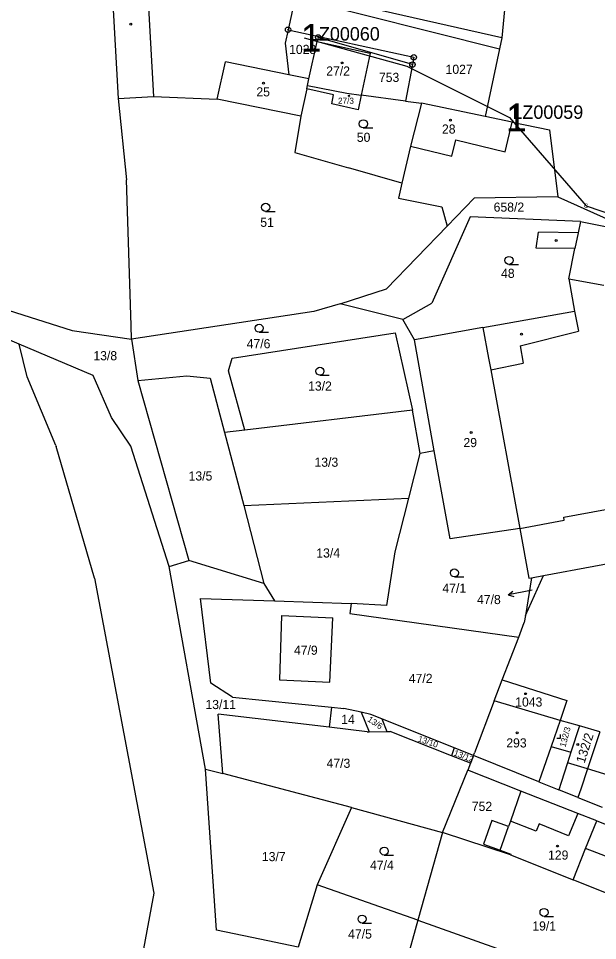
# Model space of a CAD drawing. Extents: x -738131 to -734179, y -1033447 to -1030078.
# Drawn here: x -736374.8 to -736266.9, y -1032166.9 to -1031995.2 of the extents above; entities that cross this region are included whole.
import ezdxf

# ---------------------------------------------------------------- set-up
doc = ezdxf.new("R2010")
doc.units = 0
for name, color, linetype in [('ftf_2010', 7, 'Continuous'), ('ftf_2050', 7, 'Continuous'), ('ftf_3010', 7, 'Continuous'), ('ftf_3010_ftf_3010_gtda_3015_gtda_3015_1', 7, 'Continuous'), ('ftf_3240', 7, 'Continuous'), ('Vrstva 1', 7, 'Continuous'), ('Vrstva 2', 7, 'Continuous'), ('Vrstva 3', 7, 'Continuous'), ('Vrstva 4', 7, 'Continuous'), ('Vrstva 5', 7, 'Continuous'), ('Vrstva 7', 7, 'Continuous'), ('Vrstva 8', 7, 'Continuous')]:
    doc.layers.add(name, color=color, linetype=linetype)

msp = doc.modelspace()

# ---------------------------------------------------------------- linework, layer by layer
at = {"layer": 'ftf_2010'}
msp.add_lwpolyline([(-736321.57, -1031998.83), (-736302.42, -1032004.14), (-736283.32, -1032013.66)], dxfattribs=at)
at = {"layer": 'ftf_2050'}
msp.add_lwpolyline([(-736283.32, -1032013.66), (-736269.03, -1032030.1), (-736251.9, -1032035.95), (-736234.64, -1032039.77)], dxfattribs=at)
at = {"layer": 'Vrstva 1'}
for points in [[(-736357.65, -1031984.69), (-736356.24, -1032010.13)], [(-736323.24, -1031991.27), (-736324.58, -1031997.32)], [(-736323.24, -1031991.27), (-736285.15, -1032000.89)], [(-736284.71, -1031998.81), (-736311.45, -1031992.83)], [(-736284.09, -1031992.29), (-736284.71, -1031998.81)], [(-736324.58, -1031997.32), (-736325.13, -1031999.84)], [(-736324.58, -1031997.32), (-736301.14, -1032002.45)], [(-736325.13, -1031999.84), (-736324.41, -1032005.73)], [(-736320.68, -1032006.49), (-736319.14, -1031999.54)], [(-736318.96, -1031998.76), (-736319.14, -1031999.54)], [(-736319.14, -1031999.54), (-736309.26, -1032001.7)], [(-736301.39, -1032003.81), (-736318.96, -1031998.76)], [(-736284.71, -1031998.81), (-736285.15, -1032000.89)], [(-736309.26, -1032001.7), (-736310.95, -1032009.49)], [(-736285.15, -1032000.89), (-736287.83, -1032013.47)], [(-736301.14, -1032002.45), (-736301.39, -1032003.81)], [(-736301.39, -1032003.81), (-736302.66, -1032010.6)], [(-736320.68, -1032006.49), (-736324.41, -1032005.73)], [(-736320.95, -1032007.71), (-736320.68, -1032006.49)], [(-736321.09, -1032008.35), (-736322.22, -1032013.44)], [(-736321.09, -1032008.35), (-736320.95, -1032007.71)], [(-736316.09, -1032009.46), (-736321.09, -1032008.35)], [(-736320.95, -1032007.71), (-736313.62, -1032009.13)], [(-736356.24, -1032010.13), (-736349.64, -1032009.76)], [(-736356.24, -1032010.13), (-736354.69, -1032025.26)], [(-736349.64, -1032009.76), (-736337.8, -1032010.25)], [(-736322.22, -1032013.44), (-736337.8, -1032010.25)], [(-736316.44, -1032011.15), (-736316.09, -1032009.46)], [(-736313.62, -1032009.13), (-736310.95, -1032009.49)], [(-736310.95, -1032009.49), (-736311.54, -1032012.22)], [(-736302.66, -1032010.6), (-736310.95, -1032009.49)], [(-736311.54, -1032012.22), (-736316.44, -1032011.15)], [(-736302.66, -1032010.6), (-736299.69, -1032010.99)], [(-736299.69, -1032010.99), (-736301.74, -1032018.99)], [(-736287.83, -1032013.47), (-736299.69, -1032010.99)], [(-736322.22, -1032013.44), (-736323.31, -1032020.18)], [(-736282.79, -1032014.52), (-736287.83, -1032013.47)], [(-736282.79, -1032014.52), (-736275.85, -1032015.97)], [(-736275.85, -1032015.97), (-736274.28, -1032028.47)], [(-736323.31, -1032020.18), (-736313.32, -1032023.06)], [(-736301.74, -1032018.99), (-736303.36, -1032025.92)], [(-736303.36, -1032025.92), (-736313.32, -1032023.06)], [(-736353.81, -1032052.38), (-736354.69, -1032025.26)], [(-736303.36, -1032025.92), (-736304.02, -1032028.72)], [(-736304.02, -1032028.72), (-736295.89, -1032030.28)], [(-736289.89, -1032028.72), (-736294.94, -1032033.92)], [(-736274.28, -1032028.47), (-736289.89, -1032028.72)], [(-736274.28, -1032028.47), (-736259.19, -1032035.19)], [(-736295.89, -1032030.28), (-736294.94, -1032033.92)], [(-736290.66, -1032032.19), (-736297.75, -1032048.25)], [(-736270.09, -1032033.01), (-736290.66, -1032032.19)], [(-736294.94, -1032033.92), (-736306.24, -1032045.57)], [(-736270.09, -1032033.01), (-736270.52, -1032035.12)], [(-736270.09, -1032033.01), (-736259.19, -1032035.19)], [(-736278.36, -1032038), (-736277.91, -1032035)], [(-736270.52, -1032035.12), (-736277.91, -1032035)], [(-736271.11, -1032038.07), (-736278.36, -1032038)], [(-736272.24, -1032043.71), (-736271.11, -1032038.07)], [(-736272.24, -1032043.71), (-736271.17, -1032049.76)], [(-736374.67, -1032055.87), (-736398.21, -1032045.87)], [(-736314.89, -1032048.34), (-736306.24, -1032045.57)], [(-736383.28, -1032047.51), (-736364.84, -1032053.35)], [(-736319.79, -1032049.77), (-736353.73, -1032054.93)], [(-736314.89, -1032048.34), (-736319.79, -1032049.77)], [(-736303.21, -1032051.27), (-736314.89, -1032048.34)], [(-736303.21, -1032051.27), (-736297.75, -1032048.25)], [(-736288.25, -1032052.79), (-736271.17, -1032049.76)], [(-736301.04, -1032055.06), (-736303.21, -1032051.27)], [(-736353.73, -1032054.93), (-736353.81, -1032052.38)], [(-736288.25, -1032052.79), (-736301.04, -1032055.06)], [(-736364.84, -1032053.35), (-736353.73, -1032054.93)], [(-736353.73, -1032054.93), (-736352.57, -1032062.65)], [(-736334.98, -1032058.48), (-736304.59, -1032053.78)], [(-736304.59, -1032053.78), (-736301.36, -1032068.16)], [(-736373.2, -1032061.95), (-736374.67, -1032055.87)], [(-736360.88, -1032061.73), (-736374.67, -1032055.87)], [(-736297.33, -1032075.77), (-736301.04, -1032055.06)], [(-736335.66, -1032060.83), (-736334.98, -1032058.48)], [(-736357.46, -1032069.53), (-736360.88, -1032061.73)], [(-736352.57, -1032062.65), (-736343.45, -1032061.78)], [(-736343.45, -1032061.78), (-736339.08, -1032062.24)], [(-736332.63, -1032071.9), (-736335.66, -1032060.83)], [(-736367.85, -1032074.72), (-736373.2, -1032061.95)], [(-736352.57, -1032062.65), (-736343.07, -1032096.14)], [(-736339.08, -1032062.24), (-736336.39, -1032072.35)], [(-736301.36, -1032068.16), (-736332.63, -1032071.9)], [(-736299.95, -1032076.23), (-736301.36, -1032068.16)], [(-736353.87, -1032074.87), (-736357.46, -1032069.53)], [(-736332.63, -1032071.9), (-736336.39, -1032072.35)], [(-736336.39, -1032072.35), (-736332.79, -1032085.91)], [(-736367.85, -1032074.72), (-736367.79, -1032074.92)], [(-736360.62, -1032099.46), (-736367.79, -1032074.92)], [(-736346.73, -1032097.26), (-736353.87, -1032074.87)], [(-736302.07, -1032084.56), (-736299.95, -1032076.23)], [(-736297.33, -1032075.77), (-736299.95, -1032076.23)], [(-736294.39, -1032092.15), (-736297.33, -1032075.77)], [(-736332.79, -1032085.91), (-736302.07, -1032084.56)], [(-736332.79, -1032085.91), (-736329.06, -1032100.43)], [(-736304.61, -1032094.54), (-736302.07, -1032084.56)], [(-736281.4, -1032090.23), (-736294.39, -1032092.15)], [(-736281.4, -1032090.23), (-736279.68, -1032099.47)], [(-736276.96, -1032098.96), (-736239.45, -1032092.03)], [(-736346.73, -1032097.26), (-736343.07, -1032096.14)], [(-736329.06, -1032100.43), (-736343.07, -1032096.14)], [(-736306.15, -1032104.53), (-736304.61, -1032094.54)], [(-736339.94, -1032135.02), (-736346.73, -1032097.26)], [(-736360.62, -1032099.46), (-736351.12, -1032149.84)], [(-736280.33, -1032106.39), (-736276.96, -1032098.96)], [(-736279.21, -1032099.38), (-736280.33, -1032106.39)], [(-736279.68, -1032099.47), (-736279.21, -1032099.38)], [(-736279.21, -1032099.38), (-736276.96, -1032098.96)], [(-736329.06, -1032100.43), (-736327.12, -1032103.7)], [(-736338.98, -1032119.02), (-736340.89, -1032103.24)], [(-736340.89, -1032103.24), (-736327.12, -1032103.7)], [(-736327.12, -1032103.7), (-736312.79, -1032104.16)], [(-736312.79, -1032104.16), (-736313.07, -1032106.06)], [(-736306.15, -1032104.53), (-736312.79, -1032104.16)], [(-736325.79, -1032106.38), (-736326.18, -1032118.41)], [(-736325.79, -1032106.38), (-736316.26, -1032106.81)], [(-736313.07, -1032106.06), (-736281.58, -1032110.42)], [(-736280.33, -1032106.39), (-736280.55, -1032107.74)], [(-736316.77, -1032118.81), (-736316.26, -1032106.81)], [(-736281.58, -1032110.42), (-736280.55, -1032107.74)], [(-736284.65, -1032118.38), (-736281.58, -1032110.42)], [(-736326.18, -1032118.41), (-736316.77, -1032118.81)], [(-736286.14, -1032122.3), (-736284.65, -1032118.38)], [(-736284.65, -1032118.38), (-736272.65, -1032122.22)], [(-736334.94, -1032121.6), (-736338.98, -1032119.02)], [(-736334.94, -1032121.6), (-736316.47, -1032123.48)], [(-736316.47, -1032123.48), (-736316.94, -1032127.22)], [(-736316.47, -1032123.48), (-736314.21, -1032123.71)], [(-736286.14, -1032122.3), (-736289.83, -1032132)], [(-736273.89, -1032125.98), (-736286.14, -1032122.3)], [(-736272.65, -1032122.22), (-736273.89, -1032125.98)], [(-736316.94, -1032127.22), (-736337.57, -1032124.78)], [(-736336.75, -1032135.82), (-736337.57, -1032124.78)], [(-736310.93, -1032124.43), (-736314.21, -1032123.71)], [(-736310.93, -1032124.43), (-736309.43, -1032128.06)], [(-736309.13, -1032124.82), (-736310.93, -1032124.43)], [(-736307.11, -1032125.63), (-736309.13, -1032124.82)], [(-736293.61, -1032131.06), (-736307.11, -1032125.63)], [(-736307.11, -1032125.63), (-736306.14, -1032128.03)], [(-736273.89, -1032125.98), (-736275.55, -1032130.78)], [(-736270.28, -1032126.95), (-736273.89, -1032125.98)], [(-736270.28, -1032126.95), (-736271.86, -1032131.86)], [(-736266.49, -1032128.05), (-736270.28, -1032126.95)], [(-736309.81, -1032128.06), (-736316.94, -1032127.22)], [(-736309.81, -1032128.06), (-736309.43, -1032128.06)], [(-736309.43, -1032128.06), (-736306.14, -1032128.03)], [(-736306.14, -1032128.03), (-736305.57, -1032128.03)], [(-736294.1, -1032132.52), (-736305.57, -1032128.03)], [(-736266.49, -1032128.05), (-736268.77, -1032134.98)], [(-736293.61, -1032131.06), (-736294.1, -1032132.52)], [(-736290.32, -1032132.38), (-736293.61, -1032131.06)], [(-736290.02, -1032132.5), (-736289.83, -1032132)], [(-736275.55, -1032130.78), (-736277.39, -1032136.12)], [(-736271.86, -1032131.86), (-736272.5, -1032133.84)], [(-736290.55, -1032133.91), (-736294.1, -1032132.52)], [(-736290.55, -1032133.91), (-736291.05, -1032135.21)], [(-736290.02, -1032132.5), (-736290.55, -1032133.91)], [(-736290.02, -1032132.5), (-736290.32, -1032132.38)], [(-736277.83, -1032137.39), (-736290.02, -1032132.5)], [(-736272.5, -1032133.84), (-736273.68, -1032137.51)], [(-736339.94, -1032135.02), (-736336.75, -1032135.82)], [(-736337.93, -1032165.02), (-736339.94, -1032135.02)], [(-736295.8, -1032146.81), (-736291.05, -1032135.21)], [(-736281.21, -1032139.1), (-736291.05, -1032135.21)], [(-736268.77, -1032134.98), (-736270.01, -1032138.74)], [(-736312.74, -1032142.19), (-736336.75, -1032135.82)], [(-736277.39, -1032136.12), (-736277.83, -1032137.39)], [(-736277.83, -1032137.39), (-736274.12, -1032138.88)], [(-736281.21, -1032139.1), (-736283.13, -1032144.72)], [(-736270.58, -1032143.29), (-736281.21, -1032139.1)], [(-736273.68, -1032137.51), (-736274.12, -1032138.88)], [(-736270.56, -1032140.31), (-736274.12, -1032138.88)], [(-736270.01, -1032138.74), (-736270.56, -1032140.31)], [(-736270.56, -1032140.31), (-736266.05, -1032142.12)], [(-736312.74, -1032142.19), (-736319.15, -1032156.54)], [(-736312.74, -1032142.19), (-736295.8, -1032146.81)], [(-736267.01, -1032144.65), (-736270.58, -1032143.29)], [(-736286.6, -1032144.61), (-736288.12, -1032148.99)], [(-736283.48, -1032145.72), (-736286.6, -1032144.61)], [(-736283.13, -1032144.72), (-736283.48, -1032145.72)], [(-736269.12, -1032149.8), (-736267.01, -1032144.65)], [(-736267.01, -1032144.65), (-736255.26, -1032149.31)], [(-736295.8, -1032146.81), (-736300.36, -1032163.17)], [(-736283.11, -1032150.98), (-736295.8, -1032146.81)], [(-736288.12, -1032148.99), (-736285.04, -1032150.08)], [(-736351.12, -1032149.84), (-736349.56, -1032158.09)], [(-736285.04, -1032150.08), (-736283.06, -1032150.84)], [(-736283.06, -1032150.84), (-736283.11, -1032150.98)], [(-736283.11, -1032150.98), (-736271.44, -1032155.66)], [(-736271.44, -1032155.66), (-736269.12, -1032149.8)], [(-736259.05, -1032160.59), (-736271.44, -1032155.66)], [(-736319.15, -1032156.54), (-736322.71, -1032168.15)], [(-736300.36, -1032163.17), (-736319.15, -1032156.54)], [(-736349.56, -1032158.09), (-736352.54, -1032173.8)], [(-736300.36, -1032163.17), (-736302.67, -1032171.47)], [(-736300.36, -1032163.17), (-736271.96, -1032173.23)], [(-736331.32, -1032166.39), (-736337.93, -1032165.02)], [(-736322.71, -1032168.15), (-736331.32, -1032166.39)]]:
    msp.add_lwpolyline(points, dxfattribs=at)
at = {"layer": 'Vrstva 3'}
for p, q in [((-736310.55, -1032015.6), (-736308.8, -1032015.6)), ((-736328.75, -1032031.15), (-736327, -1032031.15)), ((-736283.4, -1032041.03), (-736281.65, -1032041.03)), ((-736329.97, -1032053.66), (-736328.22, -1032053.66)), ((-736318.64, -1032061.66), (-736316.89, -1032061.66)), ((-736293.57, -1032099.22), (-736291.82, -1032099.22)), ((-736273.8, -1032129.24), (-736273.8, -1032128.57)), ((-736274.47, -1032129.24), (-736273.8, -1032129.24)), ((-736306.66, -1032151.03), (-736304.91, -1032151.03)), ((-736276.87, -1032162.45), (-736275.12, -1032162.45)), ((-736310.78, -1032163.69), (-736309.03, -1032163.69))]:
    msp.add_line(p, q, dxfattribs=at)
for centre in [(-736310.55, -1032014.85), (-736328.75, -1032030.4), (-736283.4, -1032040.28), (-736329.97, -1032052.91), (-736318.64, -1032060.91), (-736293.57, -1032098.47), (-736306.66, -1032150.28), (-736276.87, -1032161.7), (-736310.78, -1032162.94)]:
    msp.add_circle(centre, 0.75, dxfattribs=at)
at = {"layer": 'Vrstva 4'}
for points in [[(-736351.06, -1031984.32), (-736349.64, -1032009.76)], [(-736337.8, -1032010.25), (-736336.23, -1032003.31)], [(-736324.41, -1032005.73), (-736336.23, -1032003.31)], [(-736284.11, -1032020.04), (-736282.79, -1032014.52)], [(-736294.04, -1032020.84), (-736293.32, -1032017.83)], [(-736293.32, -1032017.83), (-736284.11, -1032020.04)], [(-736301.74, -1032018.99), (-736294.04, -1032020.84)], [(-736270.52, -1032035.12), (-736271.11, -1032038.07)], [(-736272.24, -1032043.71), (-736265.75, -1032044.88)], [(-736271.17, -1032049.76), (-736270.45, -1032053.47)], [(-736288.25, -1032052.79), (-736287.19, -1032058.5)], [(-736281.33, -1032056.18), (-736270.45, -1032053.47)], [(-736281.33, -1032056.18), (-736280.76, -1032059.4)], [(-736287.19, -1032058.5), (-736286.8, -1032060.63)], [(-736286.8, -1032060.63), (-736280.76, -1032059.4)], [(-736286.8, -1032060.63), (-736281.4, -1032090.23)], [(-736273.21, -1032088.09), (-736237.38, -1032081.5)], [(-736281.4, -1032090.23), (-736273.1, -1032088.68)], [(-736273.1, -1032088.68), (-736273.21, -1032088.09)], [(-736275.55, -1032130.78), (-736271.86, -1032131.86)], [(-736268.77, -1032134.98), (-736272.5, -1032133.84)], [(-736264.14, -1032136.41), (-736268.77, -1032134.98)], [(-736270.58, -1032143.29), (-736272.31, -1032147.46)], [(-736285.04, -1032150.08), (-736283.48, -1032145.72)], [(-736278.32, -1032146.59), (-736283.13, -1032144.72)], [(-736277.77, -1032145.21), (-736278.32, -1032146.59)], [(-736272.31, -1032147.46), (-736277.77, -1032145.21)], [(-736256.99, -1032154.45), (-736269.12, -1032149.8)]]:
    msp.add_lwpolyline(points, dxfattribs=at)
at = {"layer": 'Vrstva 5'}
for centre, radius in [((-736353.9, -1031996.27), 0.175), ((-736314.52, -1032003.52), 0.175), ((-736329.14, -1032007.27), 0.175), ((-736313.21, -1032009.64), 0.117), ((-736294.33, -1032014.18), 0.175), ((-736274.6, -1032036.57), 0.175), ((-736281.07, -1032054.01), 0.175), ((-736290.43, -1032072.31), 0.175), ((-736280.3, -1032120.97), 0.175), ((-736281.89, -1032128.25), 0.175), ((-736270.59, -1032130.41), 0.175), ((-736274.35, -1032149.34), 0.175)]:
    msp.add_circle(centre, radius, dxfattribs=at)
at = {"layer": 'Vrstva 7'}
for p, q in [((-736283.56, -1032102.58), (-736282.67, -1032101.89)), ((-736280.61, -1032102), (-736283.56, -1032102.58)), ((-736283.56, -1032102.58), (-736282.48, -1032102.88))]:
    msp.add_line(p, q, dxfattribs=at)
msp.add_lwpolyline([(-736279.05, -1032101.7), (-736280.61, -1032102)], dxfattribs=at)
at = {"layer": 'Vrstva 8'}
for centre, radius in [((-736324.58, -1031997.32), 0.5), ((-736324.58, -1031997.32), 0.0303), ((-736318.96, -1031998.76), 0.5), ((-736318.96, -1031998.76), 0.0303), ((-736301.39, -1032003.81), 0.5), ((-736301.14, -1032002.45), 0.5), ((-736301.14, -1032002.45), 0.0303), ((-736301.39, -1032003.81), 0.0303)]:
    msp.add_circle(centre, radius, dxfattribs=at)

# ---------------------------------------------------------------- texts
at = {"layer": 'ftf_3010'}
for p in [(-736322.22, -1032001.43), (-736283.97, -1032016.26)]:
    msp.add_text('1', height=5.2, dxfattribs=at).set_placement(p)
at = {"layer": 'ftf_3010_ftf_3010_gtda_3015_gtda_3015_1'}
for s, p in [('LZ00060', (-736320.68, -1031999.34)), ('LZ00059', (-736282.76, -1032013.92))]:
    msp.add_text(s, height=2.5, dxfattribs=at).set_placement(p)
at = {"layer": 'ftf_3240'}
msp.add_text('G', height=0.8, dxfattribs=at).set_placement((-736269.43, -1032030.5))
at = {"layer": 'Vrstva 2'}
for s, height, p in [('1028', 1.7, (-736324.38, -1032001.84)), ('27/2', 1.7, (-736317.46, -1032005.86)), ('1027', 1.7, (-736295.22, -1032005.54)), ('753', 1.7, (-736307.64, -1032007.05)), ('25', 1.7, (-736330.48, -1032009.74)), ('27/3', 1.14, (-736315.27, -1032011.12)), ('28', 1.7, (-736295.89, -1032016.67)), ('50', 1.7, (-736311.76, -1032018.21)), ('658/2', 1.7, (-736286.26, -1032031.21)), ('51', 1.7, (-736329.75, -1032034.03)), ('48', 1.7, (-736284.88, -1032043.54)), ('47/6', 1.7, (-736332.29, -1032056.64)), ('13/8', 1.7, (-736360.86, -1032058.88)), ('13/2', 1.7, (-736320.84, -1032064.53)), ('29', 1.7, (-736291.89, -1032075.05)), ('13/3', 1.7, (-736319.65, -1032078.71)), ('13/5', 1.7, (-736343.11, -1032081.27)), ('13/4', 1.7, (-736319.31, -1032095.61)), ('47/1', 1.7, (-736295.81, -1032102.17)), ('47/8', 0.1, (-736279.19, -1032101.7)), ('47/9', 1.7, (-736323.48, -1032113.72)), ('47/2', 1.7, (-736302.08, -1032118.97)), ('1043', 1.7, (-736282.24, -1032123.36)), ('13/11', 1.7, (-736339.97, -1032123.83)), ('14', 1.7, (-736314.68, -1032126.6)), ('293', 1.7, (-736283.9, -1032130.98)), ('47/3', 1.7, (-736317.4, -1032134.77)), ('752', 1.7, (-736290.33, -1032142.8)), ('13/7', 1.7, (-736329.45, -1032152.15)), ('129', 1.7, (-736276.12, -1032151.87)), ('47/4', 1.7, (-736309.3, -1032153.75)), ('47/5', 1.7, (-736313.38, -1032166.57)), ('19/1', 1.7, (-736279.05, -1032165.07))]:
    msp.add_text(s, height=height, dxfattribs=at).set_placement(p)
for s, height, rotation, p in [('13/6', 1.14, 325.7132, (-736309.88, -1032126.01)), ('132/3', 1.14, 75.3058, (-736272.87, -1032131)), ('132/2', 1.7, 72.2996, (-736269.33, -1032134.04)), ('13/10', 1.14, 341.565, (-736300.47, -1032129.84)), ('13/12', 1.14, 339.4716, (-736293.8, -1032132.45))]:
    msp.add_text(s, height=height, rotation=rotation, dxfattribs=at).set_placement(p)
at = {"layer": 'Vrstva 7'}
msp.add_text('47/8', height=1.7, dxfattribs=at).set_placement((-736289.36, -1032104.28))

doc.saveas('drawing.dxf')
